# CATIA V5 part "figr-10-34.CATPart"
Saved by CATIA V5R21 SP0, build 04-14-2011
Part number: Part1
Bounding box of the stored display mesh (mm): x 0 to 100, y -43.492 to 31.433, z -3.653 to 11.537
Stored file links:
  D:\CATIA V5R21 E-RESOURCES\CATIA-V5R21\catia-v5r21-prt\c10-catia-v5r20-prt\c10-catia-v5r21-figr-10-34.CATPart
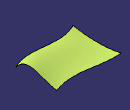
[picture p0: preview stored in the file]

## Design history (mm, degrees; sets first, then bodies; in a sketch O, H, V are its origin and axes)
Set1
  Sketch1 on yz-plane, origin (0, 0, 0), H (0, 1, 0), V (0, 0, 1)
  Plane1: type Offset, RefPlane yz-plane, Offset 100
  Sketch2 on xy-plane, origin (0, 0, 0), H (1, 0, 0), V (0, 1, 0)
    spline S1 through (0, 31.0443) (19.7053, 31.0443) (51.809, 26.4574) (100, 31.0443)
    reference intersected line E1 through (100, 0) direction (0, 1) from Plane1
    point P1 (0, 31.0443)
    point P2 (100, 31.0443)
    coincidence: P1 V, P2 E1
  Sketch3 on xy-plane, origin (0, 0, 0), H (1, 0, 0), V (0, 1, 0)
    spline S1 through (0, -43.492) (26.209, -36.2295) (80.3728, -38.1407) (100, -32.0249)
    reference intersected line E1 through (100, 0) direction (0, 1) from Plane1
    point P1 (0, -43.492)
    point P2 (100, -32.0249)
    coincidence: P1 V, P2 E1
  Sketch4 on Plane1, origin (100, 0, 0), H (0, 1, 0), V (0, 0, 1)
    spline S1 through (-32.0249, 0) (-14.5305, 11.3827) (11.9668, 5.3652) (31.0443, 0)
    reference projected point E1 (31.0443, 0) from vertex of Sketch2
    reference projected point E2 (-32.0249, 0) from vertex of Sketch3
    point P1 (-32.0249, 0)
    point P2 (31.0443, 0)
    coincidence: P1 H, P2 H, P2 E1, P1 E2
  Sketch5 on yz-plane, origin (0, 0, 0), H (0, 1, 0), V (0, 0, 1)
    spline S1 through (31.0443, 0) (7.4727, -3.1675) (-43.492, 0)
    reference projected point E1 (-43.492, 0) from vertex of Sketch3
    reference projected point E2 (31.0443, 0) from vertex of Sketch2
    point P1 (31.0443, 0)
    point P2 (-43.492, 0)
    coincidence: P1 H, P2 H, P2 E1, P1 E2
  Fill1: Boundary (Sketch5; Sketch3; Sketch4; Sketch2)
Body1 (main body)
